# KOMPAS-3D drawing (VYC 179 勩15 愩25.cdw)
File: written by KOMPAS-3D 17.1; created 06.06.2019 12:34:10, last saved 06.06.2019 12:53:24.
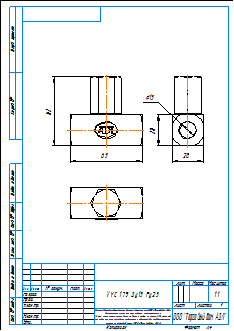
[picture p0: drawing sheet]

Sheet 1: A4, portrait

Title block, sheet 1: name: VYC 179 Ду15 Ру25; material: Внимание! Данный продукт является объектом авторского права ООО «Торговый Дом АДЛ». / Запрещается изменение, копирование, распространение / (в том числе путем копирования на другие сайты и ресурсы в Интернете) / или любое иное использование информации и объектов без предварительного / согласия правообладателя (ООО «Торговый Дом АДЛ»).; sheets: 1; organisation: ООО "Торговый дом АДЛ"; sheet format: A4; stored path: \\adlc.lan\data\АДЛ_ПКД\3D-модели\Поставщики\VYC Industrial\VYC 179\KOMPAS 2D\VYC 179 Ду15 Ру25.cdw

Views: Вид 1, Проекционный вид 2, Проекционный вид 3
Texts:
  user
Dimensions and other numbers on the sheet: 65; 62; 28; 15; 1:1; 1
